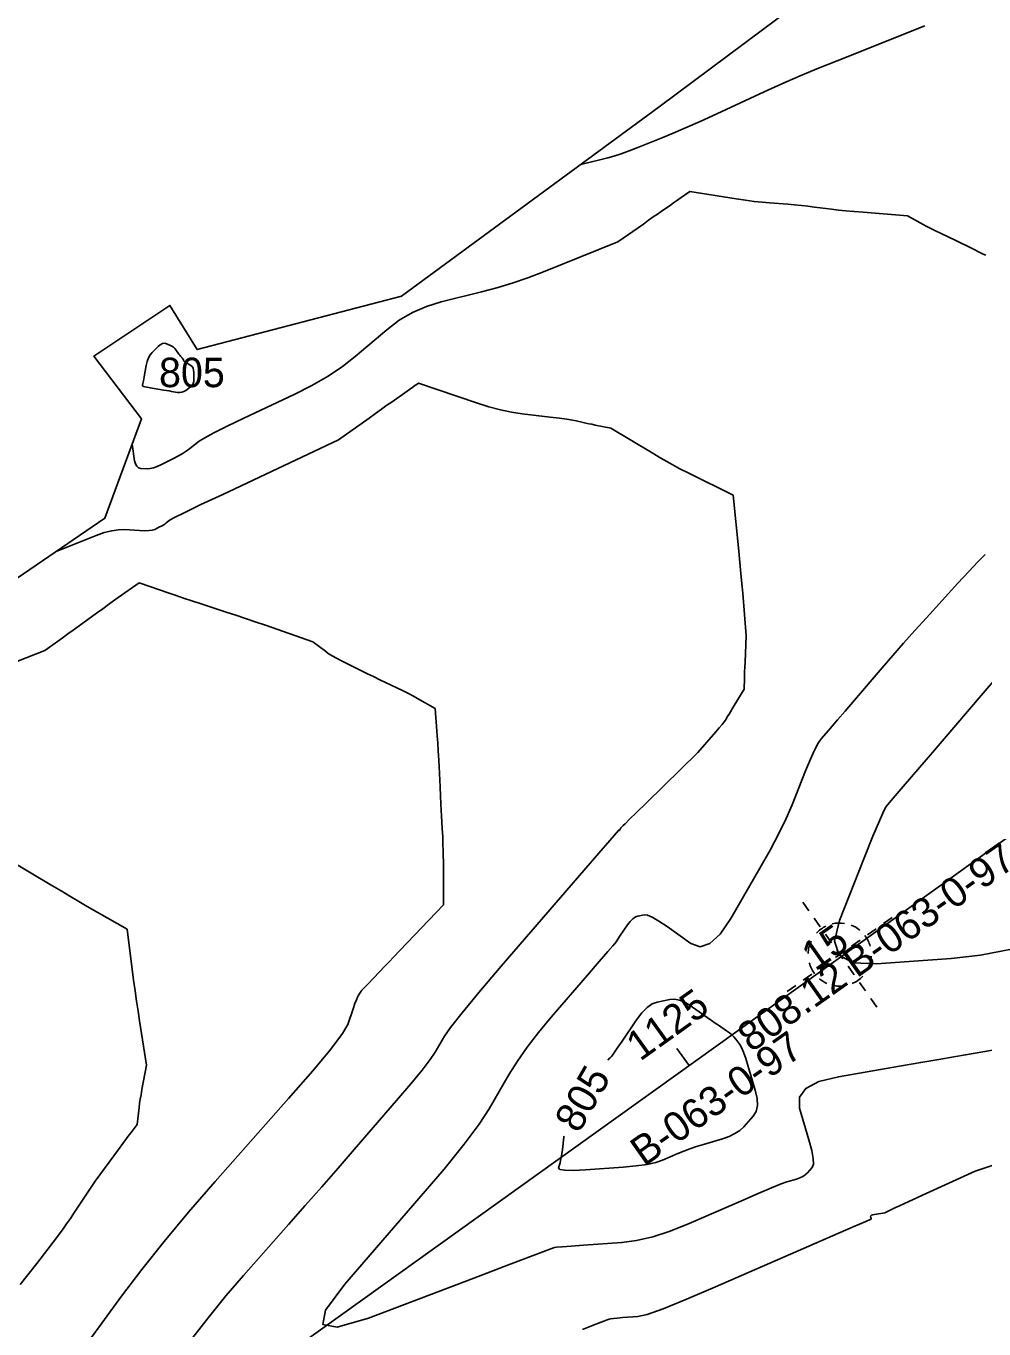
# Model space of a CAD drawing. Extents: x 2079879 to 2092887, y 778083 to 784051.
# Drawn here: x 2084331.2 to 2084422.2, y 781263.1 to 781386.8 of the extents above; entities that cross this region are included whole.
import ezdxf

# ---------------------------------------------------------------- set-up
doc = ezdxf.new("R2010")
doc.units = 0
for name, color, linetype in [('DT_X_Contour_Major', 7, 'Continuous'), ('DT_X_Contour_Minor', 7, 'Continuous'), ('DT_X_TIN_Hull', 7, 'Continuous'), ('GE_X_CL_20', 7, 'Continuous'), ('GT_Historic_Soil_Boring', 7, 'Continuous'), ('GT_Project_Text', 7, 'Continuous'), ('SV_X_Text_Comment', 7, 'Continuous'), ('SV_X_Text_Elevation', 7, 'Continuous'), ('SV_X_Text_Name', 7, 'Continuous')]:
    doc.layers.add(name, color=color, linetype=linetype)

msp = doc.modelspace()

# ---------------------------------------------------------------- linework, layer by layer
at = {"layer": 'DT_X_Contour_Major'}
for points in [[(2084383.86, 781373.69), (2084386.43, 781374.33), (2084387.02, 781374.49), (2084387.7, 781374.71), (2084388.46, 781374.98), (2084389.3, 781375.31), (2084391.66, 781376.25), (2084392.64, 781376.66), (2084393.82, 781377.17), (2084395.21, 781377.79), (2084396.79, 781378.51), (2084401.28, 781380.58), (2084402.97, 781381.35), (2084404.69, 781382.1), (2084406.44, 781382.83), (2084408.21, 781383.55), (2084416.53, 781386.85)], [(2084347.12, 781353.94), (2084347.1, 781354.16), (2084347.05, 781354.34), (2084346.96, 781354.49), (2084346.84, 781354.59), (2084346.48, 781354.82), (2084346.35, 781354.9), (2084346.27, 781354.96), (2084346.21, 781355), (2084346.19, 781355.01), (2084346.18, 781355.04), (2084346.17, 781355.05), (2084346.14, 781355.1), (2084346.12, 781355.14), (2084346.05, 781355.25), (2084346.03, 781355.29), (2084346.01, 781355.32), (2084345.99, 781355.34), (2084345.97, 781355.36), (2084345.93, 781355.38), (2084345.91, 781355.41), (2084345.86, 781355.47), (2084345.79, 781355.57), (2084345.69, 781355.69), (2084345.42, 781356.08), (2084345.31, 781356.22), (2084345.18, 781356.33), (2084345.04, 781356.43), (2084344.89, 781356.5), (2084344.47, 781356.68), (2084344.3, 781356.71), (2084344.13, 781356.68), (2084343.93, 781356.57), (2084343.73, 781356.4), (2084343.17, 781355.84), (2084342.98, 781355.61), (2084342.82, 781355.33), (2084342.69, 781354.99), (2084342.6, 781354.6), (2084342.39, 781353.51), (2084342.32, 781353.15), (2084342.27, 781352.88), (2084342.25, 781352.72), (2084342.25, 781352.66), (2084342.27, 781352.63), (2084342.32, 781352.61), (2084342.45, 781352.58), (2084342.67, 781352.54), (2084342.97, 781352.49), (2084343.89, 781352.33), (2084344.22, 781352.27), (2084344.52, 781352.22), (2084344.78, 781352.18), (2084345.01, 781352.14), (2084345.58, 781352.04), (2084345.79, 781352.02), (2084345.99, 781352.05), (2084346.18, 781352.12), (2084346.35, 781352.22), (2084346.8, 781352.57), (2084346.95, 781352.71), (2084347.05, 781352.88), (2084347.11, 781353.08), (2084347.13, 781353.3), (2084347.12, 781353.94)], [(2084423.65, 781325.29), (2084421.91, 781323.26), (2084417.08, 781317.62), (2084415.48, 781315.75), (2084414.3, 781314.37), (2084413.54, 781313.49), (2084413.2, 781313.1), (2084412.87, 781312.71), (2084412.65, 781312.3), (2084412.23, 781311.36), (2084411.62, 781309.89), (2084410.82, 781307.9), (2084408.43, 781301.88), (2084407.98, 781299.92), (2084408.41, 781298.59), (2084409.74, 781297.86), (2084411.96, 781297.75), (2084419.06, 781298.26), (2084421.82, 781298.58), (2084424.76, 781299.16)], [(2084397.32, 781281.14), (2084397.95, 781281.36), (2084398.5, 781281.63), (2084398.96, 781281.94), (2084399.35, 781282.29), (2084400.25, 781283.3), (2084400.52, 781283.74), (2084400.64, 781284.29), (2084400.61, 781284.96), (2084400.43, 781285.75), (2084399.77, 781288), (2084399.53, 781288.77), (2084399.32, 781289.37), (2084399.13, 781289.81), (2084398.97, 781290.09), (2084398.58, 781290.62), (2084398.41, 781290.82), (2084398.21, 781291.02), (2084397.98, 781291.21), (2084397.71, 781291.41), (2084396.94, 781291.93), (2084396.63, 781292.14), (2084396.27, 781292.39), (2084395.87, 781292.67), (2084395.42, 781292.98), (2084394.17, 781293.87), (2084393.7, 781294.15), (2084393.24, 781294.32), (2084392.78, 781294.39), (2084392.32, 781294.36), (2084391.11, 781294.13), (2084390.64, 781293.96), (2084390.17, 781293.62), (2084389.67, 781293.12), (2084389.16, 781292.44), (2084387.79, 781290.42), (2084387.33, 781289.76), (2084387.01, 781289.29), (2084386.81, 781289), (2084386.73, 781288.91), (2084386.71, 781288.9), (2084386.68, 781288.87), (2084386.6, 781288.79), (2084386.48, 781288.65), (2084386.45, 781288.62)], [(2084382.29, 781281.38), (2084382.27, 781281.29), (2084382.12, 781280.11), (2084382.06, 781279.71), (2084382, 781279.36), (2084381.95, 781279.08), (2084381.9, 781278.87), (2084381.76, 781278.38), (2084381.88, 781278.23), (2084382.35, 781278.15), (2084383.16, 781278.14), (2084384.32, 781278.2), (2084387.89, 781278.45), (2084389.12, 781278.56), (2084390.16, 781278.71), (2084391, 781278.89), (2084391.64, 781279.11), (2084393.09, 781279.74), (2084393.65, 781279.97), (2084394.24, 781280.19), (2084394.86, 781280.41), (2084395.52, 781280.61), (2084397.32, 781281.14)]]:
    msp.add_lwpolyline(points, dxfattribs=at)
at = {"layer": 'DT_X_Contour_Minor'}
for points in [[(2084341.26, 781347.14), (2084341.49, 781345.55), (2084341.57, 781345.25), (2084341.69, 781345.03), (2084341.85, 781344.89), (2084342.07, 781344.83), (2084342.7, 781344.79), (2084342.96, 781344.81), (2084343.27, 781344.88), (2084343.63, 781345), (2084344.04, 781345.19), (2084345.19, 781345.76), (2084345.61, 781345.98), (2084346.01, 781346.21), (2084346.38, 781346.45), (2084346.73, 781346.71), (2084347.63, 781347.4), (2084348.15, 781347.73), (2084349.03, 781348.21), (2084350.27, 781348.83), (2084351.87, 781349.6), (2084356.63, 781351.83), (2084358.33, 781352.69), (2084359.87, 781353.57), (2084361.24, 781354.49), (2084362.45, 781355.44), (2084365.46, 781358), (2084366.63, 781358.89), (2084367.87, 781359.62), (2084369.2, 781360.21), (2084370.6, 781360.64), (2084374.44, 781361.59), (2084375.89, 781361.97), (2084377.36, 781362.42), (2084378.84, 781362.93), (2084380.34, 781363.51), (2084387.38, 781366.34), (2084389.81, 781368.04), (2084390.31, 781368.39), (2084390.75, 781368.71), (2084391.15, 781368.99), (2084391.5, 781369.23), (2084392.38, 781369.84), (2084392.68, 781370.06), (2084392.96, 781370.25), (2084393.19, 781370.41), (2084393.39, 781370.55), (2084394.24, 781371.14), (2084398.61, 781370.44), (2084399.52, 781370.3), (2084400.35, 781370.19), (2084401.11, 781370.1), (2084401.79, 781370.04), (2084403.53, 781369.91), (2084404.18, 781369.85), (2084404.82, 781369.79), (2084405.44, 781369.73), (2084406.06, 781369.65), (2084407.68, 781369.44), (2084408.33, 781369.37), (2084409.04, 781369.29), (2084409.84, 781369.22), (2084410.7, 781369.15), (2084414.9, 781368.82), (2084416.38, 781368), (2084416.72, 781367.81), (2084417.12, 781367.6), (2084417.57, 781367.38), (2084418.08, 781367.14), (2084419.49, 781366.46), (2084419.99, 781366.23), (2084420.42, 781366.02), (2084420.79, 781365.84), (2084421.1, 781365.68), (2084421.82, 781365.31), (2084422.08, 781365.18), (2084422.33, 781365.07)], [(2084334.04, 781336.94), (2084337.83, 781338.44), (2084338.61, 781338.72), (2084339.32, 781338.9), (2084339.96, 781339), (2084340.53, 781339.01), (2084341.97, 781338.92), (2084342.46, 781338.9), (2084342.86, 781338.91), (2084343.17, 781338.95), (2084343.4, 781339.03), (2084343.87, 781339.26), (2084344.04, 781339.35), (2084344.2, 781339.44), (2084344.36, 781339.54), (2084344.5, 781339.65), (2084344.87, 781339.93), (2084345.28, 781340.16), (2084346.25, 781340.65), (2084347.78, 781341.38), (2084349.86, 781342.36), (2084360.86, 781347.54), (2084363.77, 781349.61), (2084364.37, 781350.05), (2084364.94, 781350.45), (2084365.46, 781350.82), (2084365.95, 781351.16), (2084367.6, 781352.33), (2084367.91, 781352.55), (2084368.12, 781352.7), (2084368.22, 781352.77), (2084368.45, 781352.93), (2084373.97, 781351.04), (2084375.13, 781350.67), (2084376.24, 781350.38), (2084377.3, 781350.16), (2084378.31, 781350.01), (2084380.95, 781349.7), (2084381.84, 781349.59), (2084382.55, 781349.5), (2084383.08, 781349.42), (2084383.42, 781349.35), (2084384.09, 781349.19), (2084384.35, 781349.13), (2084384.62, 781349.07), (2084384.92, 781349.01), (2084385.23, 781348.94), (2084386.73, 781348.64), (2084390.64, 781346.29), (2084391.48, 781345.79), (2084392.34, 781345.31), (2084393.22, 781344.83), (2084394.12, 781344.38), (2084398.34, 781342.27), (2084398.88, 781336.97), (2084398.98, 781335.87), (2084399.08, 781334.83), (2084399.17, 781333.87), (2084399.25, 781332.97), (2084399.59, 781328.93), (2084399.47, 781326.43), (2084399.45, 781325.93), (2084399.43, 781325.51), (2084399.42, 781325.17), (2084399.41, 781324.91), (2084399.39, 781323.85), (2084398.44, 781322.29), (2084398.25, 781321.98), (2084398.08, 781321.71), (2084397.95, 781321.49), (2084397.84, 781321.32), (2084397.6, 781320.92), (2084397.47, 781320.74), (2084397.28, 781320.49), (2084397.02, 781320.17), (2084396.69, 781319.79), (2084394.99, 781317.85), (2084390.1, 781313.05), (2084389.17, 781312.15), (2084388.5, 781311.49), (2084388.08, 781311.07), (2084387.9, 781310.9), (2084387.68, 781310.68), (2084387.58, 781310.5), (2084387.56, 781310.47), (2084387.54, 781310.45), (2084387.53, 781310.44), (2084387.52, 781310.44), (2084387.49, 781310.45), (2084387.49, 781310.46), (2084387.48, 781310.46), (2084387.48, 781310.47), (2084387.47, 781310.47), (2084387.47, 781310.46), (2084387.46, 781310.46), (2084387.46, 781310.46), (2084387.46, 781310.46), (2084387.46, 781310.46), (2084387.45, 781310.44), (2084387.45, 781310.44), (2084387.45, 781310.44), (2084384.76, 781307.33), (2084376.32, 781297.53), (2084374.2, 781295.04), (2084372.59, 781293.1), (2084371.49, 781291.71), (2084370.91, 781290.88), (2084370.04, 781289.38), (2084369.57, 781288.67), (2084368.8, 781287.67), (2084367.73, 781286.37), (2084366.37, 781284.77), (2084362.34, 781280.12), (2084360.81, 781278.36), (2084359.27, 781276.59), (2084357.7, 781274.8), (2084356.11, 781273), (2084351.83, 781268.16), (2084350.16, 781266.22), (2084348.37, 781264.01), (2084346.46, 781261.54)], [(2084422.28, 781336.66), (2084421.59, 781335.95), (2084420.72, 781335.03), (2084419.69, 781333.91), (2084416.7, 781330.63), (2084415.6, 781329.41), (2084414.53, 781328.21), (2084413.49, 781327.04), (2084412.49, 781325.88), (2084409.87, 781322.82), (2084408.97, 781321.77), (2084408.26, 781320.94), (2084407.73, 781320.33), (2084407.38, 781319.92), (2084406.69, 781319.13), (2084406.41, 781318.71), (2084406.07, 781318.07), (2084405.67, 781317.2), (2084405.21, 781316.1), (2084403.93, 781312.86), (2084403.37, 781311.57), (2084402.68, 781310.14), (2084401.85, 781308.56), (2084400.88, 781306.85), (2084398.11, 781302.07), (2084397.09, 781300.58), (2084396.12, 781299.69), (2084395.2, 781299.39), (2084394.32, 781299.69), (2084392.06, 781301.3), (2084391.28, 781301.82), (2084390.66, 781302.18), (2084390.2, 781302.37), (2084389.9, 781302.41), (2084389.29, 781302.3), (2084389.05, 781302.21), (2084388.81, 781302.04), (2084388.57, 781301.79), (2084388.31, 781301.45), (2084387.62, 781300.44), (2084387.39, 781300.1), (2084387.23, 781299.86), (2084387.13, 781299.72), (2084387.09, 781299.67), (2084387.08, 781299.67), (2084386.91, 781299.48), (2084386.43, 781298.92), (2084385.62, 781297.99), (2084384.5, 781296.68), (2084381.07, 781292.71), (2084379.86, 781291.25), (2084378.79, 781289.86), (2084377.86, 781288.53), (2084377.08, 781287.27), (2084375.18, 781284), (2084374.23, 781282.54), (2084372.8, 781280.64), (2084370.88, 781278.27), (2084368.49, 781275.46), (2084361.46, 781267.34), (2084359.62, 781264.86), (2084359.38, 781263.49), (2084360.74, 781263.24), (2084363.7, 781264.11), (2084373.7, 781267.91), (2084376.99, 781269.16), (2084379.35, 781270.05), (2084380.78, 781270.6), (2084381.27, 781270.79), (2084381.36, 781270.82), (2084381.56, 781270.84), (2084382.09, 781270.89), (2084382.95, 781270.95), (2084384.14, 781271.04), (2084387.76, 781271.29), (2084389.17, 781271.48), (2084390.71, 781271.84), (2084392.37, 781272.37), (2084394.15, 781273.09), (2084399.06, 781275.23), (2084400.71, 781275.94), (2084401.99, 781276.48), (2084402.9, 781276.85), (2084403.43, 781277.04), (2084404.35, 781277.31), (2084404.67, 781277.42), (2084404.95, 781277.56), (2084405.19, 781277.72), (2084405.39, 781277.9), (2084405.85, 781278.41), (2084405.96, 781278.72), (2084405.95, 781279.27), (2084405.8, 781280.04), (2084405.53, 781281.05), (2084404.65, 781284.05), (2084404.63, 781285.08), (2084405.23, 781285.92), (2084406.47, 781286.57), (2084408.33, 781287.04), (2084414.13, 781288.04), (2084416.15, 781288.39), (2084417.87, 781288.68), (2084419.29, 781288.92), (2084420.4, 781289.12), (2084422.97, 781289.56)], [(2084320.05, 781322.45), (2084332.98, 781327.53), (2084334.39, 781328.55), (2084334.73, 781328.8), (2084335.15, 781329.1), (2084335.65, 781329.46), (2084336.22, 781329.87), (2084337.87, 781331.06), (2084338.46, 781331.49), (2084339, 781331.88), (2084339.49, 781332.23), (2084339.94, 781332.55), (2084341.91, 781333.96), (2084344.78, 781332.97), (2084345.43, 781332.75), (2084346.15, 781332.51), (2084346.94, 781332.25), (2084347.8, 781331.96), (2084350.19, 781331.18), (2084351.09, 781330.88), (2084352.01, 781330.57), (2084352.95, 781330.25), (2084353.91, 781329.92), (2084358.41, 781328.35), (2084359.61, 781327.45), (2084359.89, 781327.25), (2084360.25, 781327.03), (2084360.67, 781326.8), (2084361.15, 781326.54), (2084362.52, 781325.85), (2084363.05, 781325.59), (2084363.6, 781325.32), (2084364.17, 781325.04), (2084364.77, 781324.75), (2084366.41, 781323.98), (2084366.99, 781323.7), (2084367.51, 781323.44), (2084367.97, 781323.2), (2084368.36, 781322.98), (2084370.04, 781322.01), (2084370.21, 781319.9), (2084370.24, 781319.39), (2084370.28, 781318.75), (2084370.33, 781317.99), (2084370.37, 781317.11), (2084370.5, 781314.59), (2084370.54, 781313.71), (2084370.58, 781312.95), (2084370.61, 781312.32), (2084370.64, 781311.81), (2084370.71, 781310.63), (2084370.73, 781310.22), (2084370.75, 781309.86), (2084370.76, 781309.56), (2084370.77, 781309.31), (2084370.81, 781308.31), (2084370.82, 781307.19), (2084370.82, 781306.92), (2084370.82, 781306.58), (2084370.82, 781306.18), (2084370.82, 781305.71), (2084370.83, 781303.36), (2084366.69, 781299.03), (2084366.11, 781298.42), (2084365.63, 781297.92), (2084365.26, 781297.54), (2084363.67, 781295.86), (2084363.49, 781295.68), (2084363.43, 781295.61), (2084363.37, 781295.56), (2084363.33, 781295.51), (2084363.29, 781295.47), (2084363.2, 781295.38), (2084363.17, 781295.35), (2084363.14, 781295.33), (2084363.12, 781295.31), (2084363.11, 781295.29), (2084363.08, 781295.25), (2084363.07, 781295.24), (2084363.05, 781295.22), (2084363.03, 781295.19), (2084363.01, 781295.15), (2084362.88, 781294.98), (2084362.71, 781294.72), (2084362.65, 781294.6), (2084362.56, 781294.35), (2084362.42, 781293.98), (2084362.25, 781293.48), (2084361.73, 781291.99), (2084361.23, 781291.13), (2084360.13, 781289.67), (2084358.42, 781287.61), (2084356.11, 781284.96), (2084349.13, 781277.07), (2084346.62, 781274.18), (2084344.3, 781271.4), (2084342.18, 781268.73), (2084340.26, 781266.18), (2084335.41, 781259.55)], [(2084329.54, 781307.65), (2084333.63, 781305.2), (2084334.5, 781304.68), (2084335.35, 781304.18), (2084336.18, 781303.69), (2084337, 781303.22), (2084340.78, 781301.05), (2084341.4, 781296.22), (2084341.54, 781295.2), (2084341.68, 781294.21), (2084341.82, 781293.26), (2084341.96, 781292.34), (2084342.63, 781288.12), (2084342.18, 781285.81), (2084342.1, 781285.33), (2084342.02, 781284.89), (2084341.96, 781284.49), (2084341.91, 781284.12), (2084341.73, 781282.5), (2084341.15, 781281.73), (2084340.98, 781281.51), (2084340.73, 781281.17), (2084340.38, 781280.7), (2084339.95, 781280.12), (2084337.74, 781277.12), (2084335.79, 781274.17), (2084335.39, 781273.57), (2084335.03, 781273.05), (2084334.72, 781272.6), (2084334.44, 781272.23), (2084333.77, 781271.33), (2084333.25, 781270.66), (2084332.2, 781269.31), (2084330.62, 781267.3)], [(2084384.04, 781263.04), (2084385.29, 781263.52), (2084386.07, 781263.82), (2084386.38, 781263.93), (2084386.57, 781264.01), (2084386.7, 781264.05), (2084386.96, 781264.08), (2084387.33, 781264.11), (2084387.82, 781264.15), (2084389.28, 781264.25), (2084390.16, 781264.46), (2084391.68, 781265), (2084393.85, 781265.87), (2084396.66, 781267.07), (2084405.03, 781270.72), (2084407.78, 781271.92), (2084409.75, 781272.77), (2084410.93, 781273.29), (2084411.34, 781273.46), (2084411.38, 781273.48), (2084411.4, 781273.48), (2084411.41, 781273.49), (2084411.42, 781273.5), (2084411.43, 781273.5), (2084411.45, 781273.53), (2084411.45, 781273.54), (2084411.45, 781273.57), (2084411.45, 781273.6), (2084411.43, 781273.65), (2084411.39, 781273.79), (2084411.41, 781273.83), (2084411.47, 781273.88), (2084411.6, 781273.92), (2084411.77, 781273.96), (2084412.73, 781274.12), (2084413.75, 781274.6), (2084414.07, 781274.75), (2084414.61, 781275), (2084415.36, 781275.34), (2084416.32, 781275.78), (2084421.31, 781278.08), (2084423.59, 781278.83)]]:
    msp.add_lwpolyline(points, dxfattribs=at)
at = {"layer": 'DT_X_TIN_Hull'}
msp.add_lwpolyline([(2084420.64, 781401.06), (2084391.32, 781379.16), (2084366.83, 781361.2), (2084347.43, 781356.11), (2084344.84, 781360.3), (2084337.63, 781355.5), (2084342.14, 781349.52), (2084338.65, 781340.09), (2084313.15, 781322.64), (2084284.75, 781305.36), (2084260.97, 781288.46), (2084234.45, 781269.85), (2084209.3, 781249.55), (2084182.77, 781233.3), (2084158.56, 781216.56), (2084131.63, 781197.45), (2084106.47, 781178.42), (2084083.21, 781163.08), (2084059.54, 781146.11), (2084036.93, 781129.67)], dxfattribs=at)
at = {"layer": 'GE_X_CL_20'}
for p, q in [((2079923.52, 778084.44), (2085691.45, 782217.74)), ((2084394.15, 781288.09), (2084392.99, 781289.72))]:
    msp.add_line(p, q, dxfattribs=at)
at = {"layer": 'GT_Historic_Soil_Boring'}
for p, q in [((2084405.53, 781302.81), (2084404.95, 781303.63)), ((2084406.6, 781301.29), (2084406.02, 781302.1)), ((2084412.63, 781301.58), (2084413.45, 781302.16)), ((2084407.68, 781299.76), (2084407.1, 781300.58)), ((2084411.1, 781300.51), (2084411.92, 781301.08)), ((2084409.58, 781299.43), (2084410.4, 781300.01)), ((2084408.06, 781298.36), (2084408.87, 781298.93)), ((2084408.75, 781298.24), (2084408.18, 781299.05)), ((2084406.53, 781297.28), (2084407.35, 781297.86)), ((2084409.83, 781296.71), (2084409.25, 781297.53)), ((2084403.48, 781295.13), (2084404.3, 781295.7)), ((2084405, 781296.2), (2084405.82, 781296.78)), ((2084410.9, 781295.19), (2084410.33, 781296)), ((2084411.98, 781293.66), (2084411.4, 781294.48))]:
    msp.add_line(p, q, dxfattribs=at)
for start, end in [(115.9029, 137.6568), (81.5788, 103.6503), (50.375, 68.951), (155.0428, 178.075), (15.1937, 37.0689), (335.8882, 357.2253), (195.2026, 217.3275), (229.9195, 245.8646), (259.6947, 278.8674), (293.0777, 317.1179)]:
    msp.add_arc((2084408.46, 781298.64), 3, start, end, dxfattribs=at)

# ---------------------------------------------------------------- texts
at = {"layer": 'DT_X_Contour_Major'}
msp.add_text('805', height=2.8, dxfattribs=at).set_placement((2084343.81, 781352.54))
msp.add_text('805', height=2.8, rotation=60.0877, dxfattribs=at).set_placement((2084383.67, 781281.57))
at = {"layer": 'GE_X_CL_20'}
msp.add_text('1125', height=2.8, rotation=35.6254, dxfattribs=at).set_placement((2084389.5, 781288.45))
at = {"layer": 'GT_Project_Text'}
msp.add_text('B-063-0-97', height=2.8, rotation=35.196, dxfattribs=at).set_placement((2084389.88, 781278.44))
at = {"layer": 'SV_X_Text_Comment'}
msp.add_text('B-063-0-97', height=2.8, rotation=35.196, dxfattribs=at).set_placement((2084410.08, 781296.36))
at = {"layer": 'SV_X_Text_Elevation'}
msp.add_text('808.12', height=2.8, rotation=35.196, dxfattribs=at).set_placement((2084400.06, 781289.29))
at = {"layer": 'SV_X_Text_Name'}
msp.add_text('15', height=2.8, rotation=35.196, dxfattribs=at).set_placement((2084406.14, 781297.01))

doc.saveas('drawing.dxf')
